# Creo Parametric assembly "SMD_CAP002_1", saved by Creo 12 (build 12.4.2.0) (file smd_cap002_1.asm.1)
Units: Custom; MM, KILOGRAM, SECS

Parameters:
  PTC_WM_ITERATION = "0"
  PTC_WM_VERSION = "-.0"
  PTC_WM_LIFECYCLE_STATE = "In Work"
  PTC_WM_LIFECYCLE = "MO_CADDocument"
  PTC_WM_CREATED_BY = "Maximilian Roepper (Z0017RMS: MO)"
  PTC_WM_CREATED_ON = "18-Sep-26 11:36:42 AM"
  PTC_WM_MODIFIED_BY = "Maximilian Roepper (Z0017RMS: MO)"
  PTC_WM_MODIFIED_ON = "18-Sep-26 11:36:46 AM"
  PDMLINKNUMBER = "PDM000071454971"
  PTC_WM_NUMBER = "PDM000071454971"

Other parameters: WEIGHT, WEIGHT_FACTOR, WEIGHT_ADD, MC_ERRORS, SUPPLIER

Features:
  1. coordinate system
  2. imported feature
  3. component "BODY002_1"
  4. component "CONTACT014_1"
  5. component "CONTACT015_1"

Other named items: DRW_VIEW_ORG, ROUGH-GROB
